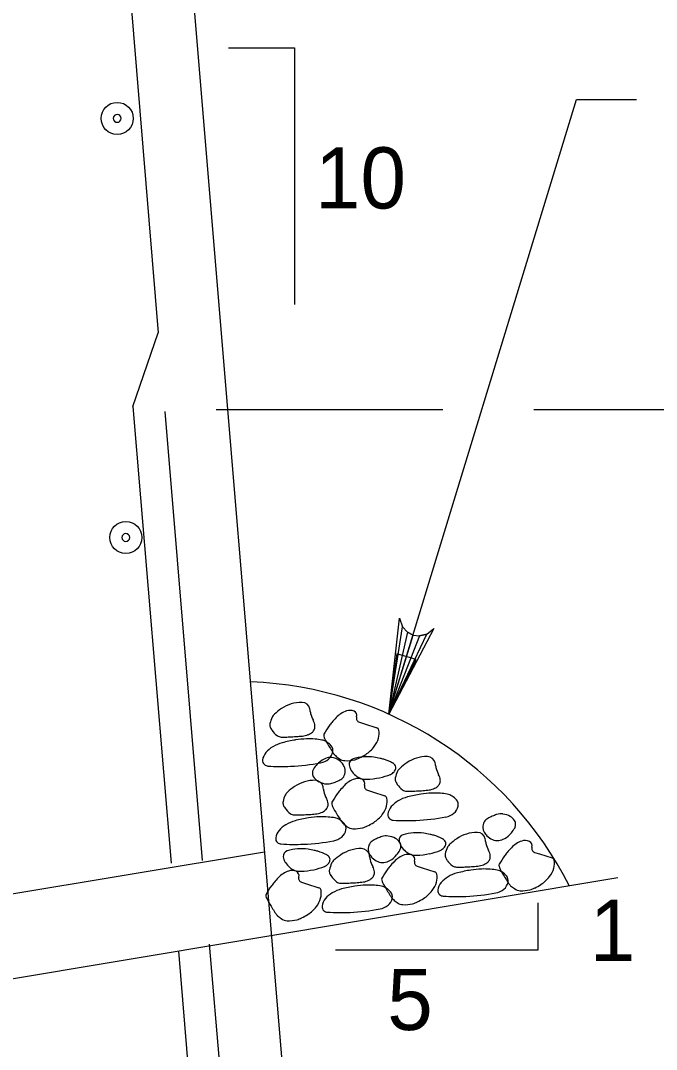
# Model space of a CAD drawing. Extents: x 634540 to 640306, y 296059 to 300275.
# Drawn here: x 639117.1 to 639148.3, y 297664.6 to 297715.1 of the extents above; entities that cross this region are included whole.
import ezdxf

# ---------------------------------------------------------------- set-up
doc = ezdxf.new("R2010")
doc.units = 0
for name, color, linetype in [('3', 7, 'Continuous'), ('5', 7, 'Continuous'), ('8', 7, 'Continuous'), ('9', 7, 'Continuous')]:
    doc.layers.add(name, color=color, linetype=linetype)

# ---------------------------------------------------------------- blocks, each defined once
blk = doc.blocks.new('B')
at = {"layer": '3'}
blk.add_circle((0, 0), 0.16, dxfattribs=at)
for start, end in [(0, 180), (180, 0)]:
    blk.add_arc((0, 0), 0.0391, start, end, dxfattribs=at)

msp = doc.modelspace()

# ---------------------------------------------------------------- linework, layer by layer
at = {"layer": '3'}
for p, q in [((639135.18, 297681.054), (639144.368, 297711.212)), ((639144.368, 297711.212), (639147.32, 297711.212)), ((639126.706, 297696.002), (639137.828, 297696.002)), ((639142.284, 297696.002), (639178.886, 297696.002))]:
    msp.add_line(p, q, dxfattribs=at)
for points in [[(639135.18, 297681.054), (639135.703, 297685.767), (639135.836, 297685.35), (639136.08, 297685.084), (639136.363, 297684.94), (639136.678, 297684.9), (639137.032, 297684.988), (639137.373, 297685.259), (639135.18, 297681.054), (639137.032, 297684.988), (639136.678, 297684.9), (639135.18, 297681.054), (639136.363, 297684.94), (639136.08, 297685.084), (639135.18, 297681.054), (639135.836, 297685.35)], [(639142.484, 297671.796), (639142.484, 297669.487), (639132.561, 297669.487)]]:
    msp.add_lwpolyline(points, dxfattribs=at)
msp.add_lwpolyline([(639136.511, 297683.736), (639135.569, 297684.021), (639135.18, 297681.054)], close=True, dxfattribs=at)
at = {"layer": '5'}
for p, q in [((639120.264, 297743.049), (639123.871, 297699.768)), ((639122.629, 297696.145), (639123.871, 297699.768)), ((639122.629, 297696.145), (639124.496, 297673.744)), ((639124.192, 297695.911), (639126.029, 297673.873)), ((639126.371, 297669.773), (639131.529, 297607.88)), ((639124.856, 297669.431), (639128.406, 297626.823))]:
    msp.add_line(p, q, dxfattribs=at)
at = {"layer": '8'}
for points in [[(639133.73, 297680.661), (639133.973, 297680.584), (639134.584, 297680.392)], [(639134.121, 297677.323), (639134.365, 297677.246), (639134.978, 297677.052)], [(639142.322, 297674.281), (639142.567, 297674.204), (639143.178, 297674.01)], [(639136.569, 297673.598), (639136.815, 297673.521), (639137.426, 297673.327)], [(639130.892, 297672.81), (639131.138, 297672.733), (639131.748, 297672.539)]]:
    msp.add_lwpolyline(points, dxfattribs=at)
for centre, radius, start, end in [((639130.906, 297679.861), 1.776, 89.5772, 124.1443), ((639130.916, 297681.243), 0.395, 11.4529, 89.5772), ((639131.561, 297678.895), 2.944, 124.1443, 132.7374), ((639129.981, 297681.053), 1.349, 6.1004, 11.4529), ((639132.224, 297681.293), 0.907, 186.1004, 192.6291), ((639133.532, 297679.993), 1.298, 109.6635, 136.4562), ((639133.264, 297680.742), 0.503, 65.9597, 109.6635), ((639133.375, 297680.99), 0.231, 342.3569, 65.9597), ((639129.649, 297680.533), 0.311, 168.4897, 199.1639), ((639130.603, 297680.338), 1.284, 153.538, 168.4897), ((639129.908, 297680.685), 0.507, 132.7374, 153.538), ((639132.641, 297681.386), 1.333, 192.6291, 208.6753), ((639130.86, 297680.412), 0.696, 6.391, 28.6753), ((639134.519, 297678.844), 2.801, 139.6491, 144.1424), ((639136.611, 297677.066), 5.547, 136.4562, 139.6491), ((639133.791, 297680.858), 0.205, 162.3569, 252.4715), ((639129.879, 297680.613), 0.554, 199.1639, 207.4728), ((639130.172, 297680.765), 0.884, 207.4728, 214.0468), ((639130.314, 297680.861), 1.056, 214.0468, 234.0353), ((639130.951, 297680.728), 0.726, 291.5731, 310.9894), ((639131.181, 297680.463), 0.375, 310.9894, 338.0834), ((639131.209, 297680.452), 0.344, 338.0834, 6.391), ((639135.051, 297678.459), 3.458, 144.1424, 152.1777), ((639134.54, 297680.251), 0.148, 9.0416, 72.4715), ((639133.759, 297680.127), 0.939, 344.9373, 9.0416), ((639130.41, 297677.906), 1.809, 104.9239, 120.8473), ((639129.91, 297680.304), 0.367, 234.0353, 268.2715), ((639130.001, 297683.307), 3.372, 268.2715, 270.9097), ((639131.614, 297673.387), 6.485, 99.0416, 104.9239), ((639129.915, 297688.68), 8.746, 270.9097, 272.5478), ((639129.667, 297694.25), 14.321, 272.5478, 273.846), ((639131.266, 297675.578), 4.267, 91.7881, 99.0416), ((639129.76, 297692.879), 12.947, 273.846, 275.2114), ((639130.843, 297681.001), 1.019, 275.2114, 291.5731), ((639131.264, 297675.642), 4.203, 86.0442, 91.7881), ((639131.359, 297677.029), 2.813, 79.021, 86.0442), ((639131.762, 297679.105), 0.698, 58.4341, 79.021), ((639132.113, 297680.01), 0.136, 152.1777, 193.5774), ((639132.45, 297680.091), 0.482, 193.5774, 207.4728), ((639137.781, 297682.863), 6.491, 207.4728, 211.2525), ((639131.646, 297678.915), 0.921, 40.5338, 58.4341), ((639133.558, 297680.181), 1.147, 321.7572, 344.9373), ((639129.688, 297678.714), 0.712, 139.2037, 172.3458), ((639130.182, 297678.288), 1.364, 120.8473, 139.2037), ((639131.833, 297679.321), 0.604, 309.5539, 349.0625), ((639147.061, 297688.495), 17.346, 211.2525, 212.2356), ((639132.067, 297679.275), 0.366, 349.0625, 40.5338), ((639135.584, 297681.257), 3.778, 212.2356, 214.3424), ((639132.939, 297679.45), 0.575, 214.3424, 227.6953), ((639132.53, 297681.403), 2.765, 295.7443, 303.0692), ((639133.08, 297680.558), 1.756, 303.0692, 321.7572), ((639129.227, 297678.776), 0.247, 172.3458, 230.2635), ((639129.269, 297678.826), 0.312, 230.2635, 266.2346), ((639129.94, 297688.571), 10.078, 272.3841, 280.7777), ((639132.598, 297677.704), 1.3, 136.4654, 149.2422), ((639132.594, 297677.708), 1.295, 117.4803, 136.4654), ((639131.661, 297679.529), 0.874, 280.7777, 309.5539), ((639132.316, 297678.244), 0.69, 91.376, 117.4803), ((639132.315, 297678.253), 0.681, 65.3457, 91.376), ((639133.746, 297680.337), 1.774, 227.6953, 235.2847), ((639132.274, 297678.163), 0.78, 41.057, 65.3457), ((639133.061, 297679.347), 0.569, 235.2847, 266.0442), ((639132.176, 297678.078), 0.91, 27.4728, 41.057), ((639133.121, 297680.214), 1.438, 266.0442, 285.2565), ((639133.5, 297678.606), 0.275, 106.8084, 186.6218), ((639134.093, 297676.642), 2.327, 81.3134, 106.8084), ((639133.144, 297680.129), 1.351, 285.2565, 295.7443), ((639133.514, 297672.851), 6.162, 78.4814, 81.3134), ((639134.288, 297676.652), 2.282, 73.8272, 78.4814), ((639134.329, 297676.794), 2.134, 61.1605, 73.8272), ((639135.187, 297678.351), 0.357, 29.8544, 61.1605), ((639137.706, 297676.239), 2.944, 124.1443, 132.7374), ((639137.05, 297677.205), 1.776, 89.5772, 124.1443), ((639137.061, 297678.587), 0.395, 11.4529, 89.5772), ((639136.125, 297678.397), 1.349, 6.1004, 11.4529), ((639129.929, 297688.848), 10.356, 266.2346, 272.3841), ((639131.763, 297678.168), 0.34, 171.9761, 209.5935), ((639131.837, 297678.157), 0.414, 149.2422, 171.9761), ((639132.587, 297678.292), 0.447, 8.0357, 27.4728), ((639132.46, 297678.274), 0.576, 337.0418, 8.0357), ((639133.808, 297678.641), 0.585, 186.6218, 200.3491), ((639133.926, 297678.685), 0.711, 200.3491, 212.797), ((639134.25, 297678.894), 1.097, 212.797, 230.2213), ((639134.078, 297680.993), 3.119, 281.8686, 292.039), ((639135.064, 297678.558), 0.491, 292.039, 317.8475), ((639135.15, 297678.48), 0.376, 317.8475, 347.2445), ((639136.747, 297677.683), 1.284, 153.538, 168.4897), ((639135.337, 297678.438), 0.183, 347.2445, 29.8544), ((639136.052, 297678.029), 0.507, 132.7374, 153.538), ((639138.369, 297678.637), 0.907, 186.1004, 192.6291), ((639138.785, 297678.73), 1.333, 192.6291, 208.6753), ((639137.005, 297677.757), 0.696, 6.391, 28.6753), ((639131.549, 297676.04), 1.776, 89.5772, 124.1443), ((639131.99, 297678.296), 0.6, 209.5935, 237.6667), ((639131.559, 297677.421), 0.395, 11.4529, 89.5772), ((639132.217, 297678.655), 1.024, 237.6667, 259.0544), ((639132.148, 297678.298), 0.661, 259.0544, 285.7584), ((639131.021, 297682.291), 4.81, 285.7584, 288.5059), ((639132.147, 297678.927), 1.262, 288.5059, 293.8705), ((639132.199, 297678.811), 1.135, 293.8705, 297.4803), ((639131.488, 297680.178), 2.676, 297.4803, 299.831), ((639132.618, 297678.207), 0.404, 299.831, 337.0418), ((639133.924, 297676.654), 1.298, 109.6635, 136.4562), ((639133.657, 297677.403), 0.503, 65.9597, 109.6635), ((639134.065, 297678.672), 0.808, 230.2213, 250.5601), ((639134.063, 297678.666), 0.802, 250.5601, 271.915), ((639133.767, 297677.651), 0.231, 342.3569, 65.9597), ((639134.183, 297677.519), 0.205, 162.3569, 252.4715), ((639133.967, 297681.52), 3.657, 271.915, 281.8686), ((639135.794, 297677.877), 0.311, 168.4897, 199.1639), ((639136.023, 297677.957), 0.554, 199.1639, 207.4728), ((639136.317, 297678.109), 0.884, 207.4728, 214.0468), ((639136.459, 297678.205), 1.056, 214.0468, 234.0353), ((639137.325, 297677.807), 0.375, 310.9894, 338.0834), ((639137.354, 297677.796), 0.344, 338.0834, 6.391), ((639131.246, 297676.517), 1.284, 153.538, 168.4897), ((639130.551, 297676.863), 0.507, 132.7374, 153.538), ((639132.204, 297675.074), 2.944, 124.1443, 132.7374), ((639130.624, 297677.232), 1.349, 6.1004, 11.4529), ((639132.868, 297677.472), 0.907, 186.1004, 192.6291), ((639133.284, 297677.565), 1.333, 192.6291, 208.6753), ((639135.443, 297675.121), 3.458, 144.1424, 152.1777), ((639134.911, 297675.505), 2.801, 139.6491, 144.1424), ((639137.004, 297673.728), 5.547, 136.4562, 139.6491), ((639136.054, 297677.648), 0.367, 234.0353, 268.2715), ((639136.145, 297680.651), 3.372, 268.2715, 270.9097), ((639137.758, 297670.731), 6.485, 99.0416, 104.9239), ((639136.06, 297686.025), 8.746, 270.9097, 272.5478), ((639135.812, 297691.594), 14.321, 272.5478, 273.846), ((639137.41, 297672.922), 4.267, 91.7881, 99.0416), ((639135.904, 297690.223), 12.947, 273.846, 275.2114), ((639136.987, 297678.345), 1.019, 275.2114, 291.5731), ((639137.408, 297672.986), 4.203, 86.0442, 91.7881), ((639137.095, 297678.072), 0.726, 291.5731, 310.9894), ((639137.504, 297674.373), 2.813, 79.021, 86.0442), ((639137.906, 297676.449), 0.698, 58.4341, 79.021), ((639130.293, 297676.711), 0.311, 168.4897, 199.1639), ((639130.522, 297676.791), 0.554, 199.1639, 207.4728), ((639131.504, 297676.591), 0.696, 6.391, 28.6753), ((639131.853, 297676.63), 0.344, 338.0834, 6.391), ((639132.506, 297676.671), 0.136, 152.1777, 193.5774), ((639132.843, 297676.752), 0.482, 193.5774, 207.4728), ((639134.932, 297676.912), 0.148, 9.0416, 72.4715), ((639134.151, 297676.788), 0.939, 344.9373, 9.0416), ((639136.326, 297675.632), 1.364, 120.8473, 139.2037), ((639136.554, 297675.25), 1.809, 104.9239, 120.8473), ((639137.79, 297676.259), 0.921, 40.5338, 58.4341), ((639138.211, 297676.62), 0.366, 349.0625, 40.5338), ((639130.815, 297676.944), 0.884, 207.4728, 214.0468), ((639130.958, 297677.04), 1.056, 214.0468, 234.0353), ((639130.553, 297676.482), 0.367, 234.0353, 268.2715), ((639130.644, 297679.486), 3.372, 268.2715, 270.9097), ((639130.558, 297684.859), 8.746, 270.9097, 272.5478), ((639130.311, 297690.428), 14.321, 272.5478, 273.846), ((639130.403, 297689.057), 12.947, 273.846, 275.2114), ((639131.486, 297677.179), 1.019, 275.2114, 291.5731), ((639131.594, 297676.906), 0.726, 291.5731, 310.9894), ((639131.824, 297676.642), 0.375, 310.9894, 338.0834), ((639138.174, 297679.524), 6.491, 207.4728, 211.2525), ((639147.453, 297685.156), 17.346, 211.2525, 212.2356), ((639133.472, 297677.219), 1.756, 303.0692, 321.7572), ((639133.951, 297676.842), 1.147, 321.7572, 344.9373), ((639135.372, 297676.12), 0.247, 172.3458, 230.2635), ((639135.832, 297676.058), 0.712, 139.2037, 172.3458), ((639137.806, 297676.873), 0.874, 280.7777, 309.5539), ((639137.977, 297676.665), 0.604, 309.5539, 349.0625), ((639140.709, 297674.879), 1.262, 111.6288, 116.9933), ((639142.016, 297671.582), 4.81, 108.8812, 111.6288), ((639140.674, 297675.507), 0.661, 82.1773, 108.8812), ((639140.625, 297675.147), 1.024, 60.7895, 82.1773), ((639130.825, 297674.466), 1.364, 120.8473, 139.2037), ((639131.053, 297674.085), 1.809, 104.9239, 120.8473), ((639132.257, 297669.566), 6.485, 99.0416, 104.9239), ((639131.909, 297671.757), 4.267, 91.7881, 99.0416), ((639131.907, 297671.82), 4.203, 86.0442, 91.7881), ((639132.003, 297673.208), 2.813, 79.021, 86.0442), ((639132.405, 297675.284), 0.698, 58.4341, 79.021), ((639132.289, 297675.094), 0.921, 40.5338, 58.4341), ((639135.977, 297677.919), 3.778, 212.2356, 214.3424), ((639133.332, 297676.112), 0.575, 214.3424, 227.6953), ((639134.139, 297676.998), 1.774, 227.6953, 235.2847), ((639132.71, 297675.454), 0.366, 349.0625, 40.5338), ((639133.536, 297676.791), 1.351, 285.2565, 295.7443), ((639132.922, 297678.064), 2.765, 295.7443, 303.0692), ((639135.413, 297676.17), 0.312, 230.2635, 266.2346), ((639136.073, 297686.192), 10.356, 266.2346, 272.3841), ((639136.084, 297685.915), 10.078, 272.3841, 280.7777), ((639140.361, 297675.515), 0.576, 160.1647, 191.1585), ((639140.2, 297675.573), 0.404, 122.9538, 160.1647), ((639141.436, 297673.667), 2.676, 120.6031, 122.9538), ((639140.651, 297674.993), 1.135, 116.9933, 120.6031), ((639140.832, 297675.518), 0.6, 32.7163, 60.7895), ((639141.051, 297675.658), 0.34, 355.0989, 32.7163), ((639140.976, 297675.665), 0.414, 332.365, 355.0989), ((639130.331, 297674.893), 0.712, 139.2037, 172.3458), ((639132.476, 297675.499), 0.604, 309.5539, 349.0625), ((639133.453, 297676.008), 0.569, 235.2847, 266.0442), ((639133.513, 297676.875), 1.438, 266.0442, 285.2565), ((639136.391, 297670.502), 4.81, 108.8812, 111.6288), ((639135.049, 297674.427), 0.661, 82.1773, 108.8812), ((639134.999, 297674.067), 1.024, 60.7895, 82.1773), ((639135.948, 297674.881), 0.275, 106.8084, 186.6218), ((639136.542, 297672.917), 2.327, 81.3134, 106.8084), ((639135.962, 297669.126), 6.162, 78.4814, 81.3134), ((639136.737, 297672.927), 2.282, 73.8272, 78.4814), ((639136.778, 297673.069), 2.134, 61.1605, 73.8272), ((639139.499, 297673.48), 1.776, 89.5772, 124.1443), ((639139.509, 297674.862), 0.395, 11.4529, 89.5772), ((639140.235, 297675.49), 0.447, 191.1585, 210.5956), ((639140.634, 297675.726), 0.91, 210.5956, 224.1798), ((639140.541, 297675.635), 0.78, 224.1798, 248.4685), ((639140.196, 297676.072), 1.295, 300.6031, 319.5882), ((639140.192, 297676.076), 1.3, 319.5882, 332.365), ((639129.87, 297674.955), 0.247, 172.3458, 230.2635), ((639129.912, 297675.005), 0.312, 230.2635, 266.2346), ((639130.572, 297685.026), 10.356, 266.2346, 272.3841), ((639130.583, 297684.749), 10.078, 272.3841, 280.7777), ((639132.305, 297675.707), 0.874, 280.7777, 309.5539), ((639134.736, 297674.435), 0.576, 160.1647, 191.1585), ((639134.574, 297674.493), 0.404, 122.9538, 160.1647), ((639135.81, 297672.586), 2.676, 120.6031, 122.9538), ((639135.026, 297673.913), 1.135, 116.9933, 120.6031), ((639135.083, 297673.799), 1.262, 111.6288, 116.9933), ((639135.206, 297674.438), 0.6, 32.7163, 60.7895), ((639136.257, 297674.916), 0.585, 186.6218, 200.3491), ((639136.375, 297674.96), 0.711, 200.3491, 212.797), ((639135.425, 297674.578), 0.34, 355.0989, 32.7163), ((639135.351, 297674.585), 0.414, 332.365, 355.0989), ((639136.699, 297675.169), 1.097, 212.797, 230.2213), ((639137.636, 297674.626), 0.357, 29.8544, 61.1605), ((639137.598, 297674.755), 0.376, 317.8475, 347.2445), ((639137.786, 297674.713), 0.183, 347.2445, 29.8544), ((639138.501, 297674.304), 0.507, 132.7374, 153.538), ((639140.154, 297672.514), 2.944, 124.1443, 132.7374), ((639138.574, 297674.672), 1.349, 6.1004, 11.4529), ((639140.818, 297674.912), 0.907, 186.1004, 192.6291), ((639141.234, 297675.005), 1.333, 192.6291, 208.6753), ((639140.504, 297675.543), 0.681, 248.4685, 274.4988), ((639140.504, 297675.552), 0.69, 274.4988, 300.6031), ((639142.125, 297673.612), 1.298, 109.6635, 136.4562), ((639141.858, 297674.361), 0.503, 65.9597, 109.6635), ((639141.968, 297674.609), 0.231, 342.3569, 65.9597), ((639142.384, 297674.477), 0.205, 162.3569, 252.4715), ((639130.271, 297674.093), 0.275, 106.8084, 186.6218), ((639130.579, 297674.129), 0.585, 186.6218, 200.3491), ((639130.864, 297672.129), 2.327, 81.3134, 106.8084), ((639130.285, 297668.338), 6.162, 78.4814, 81.3134), ((639131.06, 297672.14), 2.282, 73.8272, 78.4814), ((639131.101, 297672.282), 2.134, 61.1605, 73.8272), ((639131.958, 297673.839), 0.357, 29.8544, 61.1605), ((639134.477, 297671.727), 2.944, 124.1443, 132.7374), ((639133.822, 297672.693), 1.776, 89.5772, 124.1443), ((639133.832, 297674.074), 0.395, 11.4529, 89.5772), ((639134.609, 297674.41), 0.447, 191.1585, 210.5956), ((639132.897, 297673.885), 1.349, 6.1004, 11.4529), ((639135.008, 297674.646), 0.91, 210.5956, 224.1798), ((639134.57, 297674.992), 1.295, 300.6031, 319.5882), ((639136.373, 297672.929), 1.298, 109.6635, 136.4562), ((639134.566, 297674.996), 1.3, 319.5882, 332.365), ((639136.106, 297673.678), 0.503, 65.9597, 109.6635), ((639136.514, 297674.947), 0.808, 230.2213, 250.5601), ((639136.512, 297674.941), 0.802, 250.5601, 271.915), ((639136.216, 297673.926), 0.231, 342.3569, 65.9597), ((639136.416, 297677.795), 3.657, 271.915, 281.8686), ((639136.527, 297677.268), 3.119, 281.8686, 292.039), ((639137.513, 297674.833), 0.491, 292.039, 317.8475), ((639138.243, 297674.152), 0.311, 168.4897, 199.1639), ((639139.196, 297673.958), 1.284, 153.538, 168.4897), ((639138.472, 297674.232), 0.554, 199.1639, 207.4728), ((639139.453, 297674.032), 0.696, 6.391, 28.6753), ((639139.803, 297674.071), 0.344, 338.0834, 6.391), ((639143.644, 297672.079), 3.458, 144.1424, 152.1777), ((639143.112, 297672.463), 2.801, 139.6491, 144.1424), ((639145.204, 297670.686), 5.547, 136.4562, 139.6491), ((639130.697, 297674.173), 0.711, 200.3491, 212.797), ((639131.022, 297674.382), 1.097, 212.797, 230.2213), ((639130.836, 297674.159), 0.808, 230.2213, 250.5601), ((639130.85, 297676.481), 3.119, 281.8686, 292.039), ((639131.836, 297674.045), 0.491, 292.039, 317.8475), ((639131.921, 297673.968), 0.376, 317.8475, 347.2445), ((639133.519, 297673.17), 1.284, 153.538, 168.4897), ((639132.109, 297673.925), 0.183, 347.2445, 29.8544), ((639132.823, 297673.517), 0.507, 132.7374, 153.538), ((639135.14, 297674.125), 0.907, 186.1004, 192.6291), ((639135.556, 297674.218), 1.333, 192.6291, 208.6753), ((639134.915, 297674.555), 0.78, 224.1798, 248.4685), ((639133.776, 297673.244), 0.696, 6.391, 28.6753), ((639134.879, 297674.463), 0.681, 248.4685, 274.4988), ((639134.878, 297674.472), 0.69, 274.4988, 300.6031), ((639137.36, 297671.78), 2.801, 139.6491, 144.1424), ((639139.452, 297670.003), 5.547, 136.4562, 139.6491), ((639136.632, 297673.794), 0.205, 162.3569, 252.4715), ((639138.765, 297674.384), 0.884, 207.4728, 214.0468), ((639138.908, 297674.48), 1.056, 214.0468, 234.0353), ((639138.503, 297673.923), 0.367, 234.0353, 268.2715), ((639138.594, 297676.926), 3.372, 268.2715, 270.9097), ((639138.508, 297682.3), 8.746, 270.9097, 272.5478), ((639138.261, 297687.869), 14.321, 272.5478, 273.846), ((639138.353, 297686.498), 12.947, 273.846, 275.2114), ((639139.436, 297674.62), 1.019, 275.2114, 291.5731), ((639139.544, 297674.347), 0.726, 291.5731, 310.9894), ((639139.774, 297674.082), 0.375, 310.9894, 338.0834), ((639140.706, 297673.629), 0.136, 152.1777, 193.5774), ((639141.043, 297673.71), 0.482, 193.5774, 207.4728), ((639143.133, 297673.87), 0.148, 9.0416, 72.4715), ((639142.352, 297673.746), 0.939, 344.9373, 9.0416), ((639133.775, 297669.215), 5.547, 136.4562, 139.6491), ((639130.696, 297672.142), 1.298, 109.6635, 136.4562), ((639130.428, 297672.891), 0.503, 65.9597, 109.6635), ((639130.834, 297674.154), 0.802, 250.5601, 271.915), ((639130.539, 297673.139), 0.231, 342.3569, 65.9597), ((639130.955, 297673.007), 0.205, 162.3569, 252.4715), ((639130.739, 297677.007), 3.657, 271.915, 281.8686), ((639132.565, 297673.365), 0.311, 168.4897, 199.1639), ((639132.795, 297673.444), 0.554, 199.1639, 207.4728), ((639133.088, 297673.597), 0.884, 207.4728, 214.0468), ((639133.23, 297673.693), 1.056, 214.0468, 234.0353), ((639134.097, 297673.295), 0.375, 310.9894, 338.0834), ((639134.125, 297673.283), 0.344, 338.0834, 6.391), ((639137.892, 297671.396), 3.458, 144.1424, 152.1777), ((639137.381, 297673.187), 0.148, 9.0416, 72.4715), ((639136.6, 297673.063), 0.939, 344.9373, 9.0416), ((639138.775, 297671.907), 1.364, 120.8473, 139.2037), ((639139.003, 297671.525), 1.809, 104.9239, 120.8473), ((639140.207, 297667.006), 6.485, 99.0416, 104.9239), ((639139.859, 297669.197), 4.267, 91.7881, 99.0416), ((639139.857, 297669.261), 4.203, 86.0442, 91.7881), ((639139.953, 297670.648), 2.813, 79.021, 86.0442), ((639140.355, 297672.724), 0.698, 58.4341, 79.021), ((639146.374, 297676.482), 6.491, 207.4728, 211.2525), ((639140.239, 297672.534), 0.921, 40.5338, 58.4341), ((639155.654, 297682.114), 17.346, 211.2525, 212.2356), ((639140.66, 297672.895), 0.366, 349.0625, 40.5338), ((639141.673, 297674.177), 1.756, 303.0692, 321.7572), ((639142.152, 297673.8), 1.147, 321.7572, 344.9373), ((639132.215, 297670.608), 3.458, 144.1424, 152.1777), ((639131.683, 297670.993), 2.801, 139.6491, 144.1424), ((639131.704, 297672.4), 0.148, 9.0416, 72.4715), ((639132.826, 297673.135), 0.367, 234.0353, 268.2715), ((639132.916, 297676.139), 3.372, 268.2715, 270.9097), ((639134.53, 297666.219), 6.485, 99.0416, 104.9239), ((639132.831, 297681.512), 8.746, 270.9097, 272.5478), ((639132.583, 297687.082), 14.321, 272.5478, 273.846), ((639134.181, 297668.41), 4.267, 91.7881, 99.0416), ((639132.675, 297685.711), 12.947, 273.846, 275.2114), ((639133.759, 297673.832), 1.019, 275.2114, 291.5731), ((639134.179, 297668.473), 4.203, 86.0442, 91.7881), ((639133.867, 297673.56), 0.726, 291.5731, 310.9894), ((639134.275, 297669.861), 2.813, 79.021, 86.0442), ((639134.678, 297671.937), 0.698, 58.4341, 79.021), ((639134.954, 297672.946), 0.136, 152.1777, 193.5774), ((639135.291, 297673.027), 0.482, 193.5774, 207.4728), ((639140.622, 297675.799), 6.491, 207.4728, 211.2525), ((639134.561, 297671.747), 0.921, 40.5338, 58.4341), ((639136.4, 297673.117), 1.147, 321.7572, 344.9373), ((639138.281, 297672.333), 0.712, 139.2037, 172.3458), ((639140.426, 297672.94), 0.604, 309.5539, 349.0625), ((639144.177, 297674.877), 3.778, 212.2356, 214.3424), ((639141.533, 297673.07), 0.575, 214.3424, 227.6953), ((639142.34, 297673.956), 1.774, 227.6953, 235.2847), ((639141.737, 297673.749), 1.351, 285.2565, 295.7443), ((639141.123, 297675.022), 2.765, 295.7443, 303.0692), ((639129.277, 297672.159), 0.136, 152.1777, 193.5774), ((639129.614, 297672.24), 0.482, 193.5774, 207.4728), ((639134.945, 297675.012), 6.491, 207.4728, 211.2525), ((639130.722, 297672.329), 1.147, 321.7572, 344.9373), ((639130.923, 297672.275), 0.939, 344.9373, 9.0416), ((639133.097, 297671.12), 1.364, 120.8473, 139.2037), ((639133.326, 297670.738), 1.809, 104.9239, 120.8473), ((639149.902, 297681.431), 17.346, 211.2525, 212.2356), ((639134.749, 297672.153), 0.604, 309.5539, 349.0625), ((639138.425, 297674.194), 3.778, 212.2356, 214.3424), ((639134.983, 297672.107), 0.366, 349.0625, 40.5338), ((639135.781, 297672.387), 0.575, 214.3424, 227.6953), ((639135.371, 297674.339), 2.765, 295.7443, 303.0692), ((639135.921, 297673.494), 1.756, 303.0692, 321.7572), ((639137.82, 297672.395), 0.247, 172.3458, 230.2635), ((639137.862, 297672.445), 0.312, 230.2635, 266.2346), ((639138.522, 297682.467), 10.356, 266.2346, 272.3841), ((639138.533, 297682.19), 10.078, 272.3841, 280.7777), ((639140.255, 297673.148), 0.874, 280.7777, 309.5539), ((639141.654, 297672.967), 0.569, 235.2847, 266.0442), ((639141.714, 297673.833), 1.438, 266.0442, 285.2565), ((639144.225, 297680.643), 17.346, 211.2525, 212.2356), ((639130.244, 297672.706), 1.756, 303.0692, 321.7572), ((639132.143, 297671.608), 0.247, 172.3458, 230.2635), ((639132.604, 297671.546), 0.712, 139.2037, 172.3458), ((639134.577, 297672.361), 0.874, 280.7777, 309.5539), ((639136.588, 297673.273), 1.774, 227.6953, 235.2847), ((639135.902, 297672.283), 0.569, 235.2847, 266.0442), ((639135.962, 297673.15), 1.438, 266.0442, 285.2565), ((639135.985, 297673.065), 1.351, 285.2565, 295.7443), ((639132.748, 297673.406), 3.778, 212.2356, 214.3424), ((639130.103, 297671.599), 0.575, 214.3424, 227.6953), ((639130.91, 297672.486), 1.774, 227.6953, 235.2847), ((639130.224, 297671.496), 0.569, 235.2847, 266.0442), ((639130.308, 297672.278), 1.351, 285.2565, 295.7443), ((639129.693, 297673.552), 2.765, 295.7443, 303.0692), ((639132.185, 297671.658), 0.312, 230.2635, 266.2346), ((639132.844, 297681.68), 10.356, 266.2346, 272.3841), ((639132.856, 297681.403), 10.078, 272.3841, 280.7777), ((639130.284, 297672.363), 1.438, 266.0442, 285.2565)]:
    msp.add_arc(centre, radius, start, end, dxfattribs=at)
at = {"layer": '9'}
for p, q in [((639121.746, 297762.308), (639133.165, 297625.285)), ((639129.081, 297674.292), (639103.291, 297669.993)), ((639146.407, 297673.023), (639103.291, 297665.837))]:
    msp.add_line(p, q, dxfattribs=at)
msp.add_lwpolyline([(639127.308, 297713.737), (639130.54, 297713.737), (639130.54, 297701.153)], dxfattribs=at)
msp.add_arc((639127.685, 297664.324), 18.332, 26.9324, 87.7453, dxfattribs=at)

# ---------------------------------------------------------------- block references
at = {"layer": '3', "xscale": 4.921475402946, "yscale": 4.921475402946, "rotation": 90}
for p in [(639121.856, 297710.283), (639122.277, 297689.724)]:
    msp.add_blockref('B', p, dxfattribs=at)

# ---------------------------------------------------------------- texts
at = {"layer": '3'}
for s, height, p in [('10', 3.0001, (639131.552, 297705.864)), ('1', 3, (639145.02, 297668.956)), ('5', 3, (639135.096, 297665.566))]:
    msp.add_text(s, height=height, dxfattribs=at).set_placement(p)

doc.saveas('drawing.dxf')
